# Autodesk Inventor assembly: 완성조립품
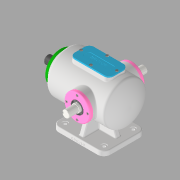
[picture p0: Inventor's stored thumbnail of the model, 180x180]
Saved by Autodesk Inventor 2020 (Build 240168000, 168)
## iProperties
Created: 2021-11
Part Number: 완성조립품
Document SubType Name: Assembly
Designer: Administrator
Author: Administrator
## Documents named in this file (14)
- C:\Users\Administrator\Desktop\71106V1028\완성조립품.iam
- C:\Users\Administrator\Desktop\71106V1028\본체.ipt
- C:\Users\Administrator\Desktop\71106V1028\베어링 6205.ipt
- 베어링 6205.ipt
- C:\Users\Administrator\Desktop\71106V1028\볼트 M4x0.7.ipt
- C:\Users\Administrator\Desktop\71106V1028\부시.ipt
- C:\Users\Administrator\Desktop\71106V1028\상부커버.ipt
- C:\Users\Administrator\Desktop\71106V1028\슬라이드 커버.ipt
- C:\Users\Administrator\Desktop\71106V1028\슬라이드.ipt
- C:\Users\Administrator\Desktop\71106V1028\오일실.ipt
- 오일실.ipt
- C:\Users\Administrator\Desktop\71106V1028\육각머리볼트 M4.ipt
- C:\Users\Administrator\Desktop\71106V1028\축 커버.ipt
- C:\Users\Administrator\Desktop\71106V1028\편심축.ipt
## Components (12 placed, 1 different names)
1. M4x0.7:1 — 각도:1
2. M4x0.7:2
3. M4x0.7:3
4. M4x0.7:4
5. M4x0.7:5 — 각도:2
6. M4x0.7:6
7. M4x0.7:7
8. M4x0.7:8
9. M4x0.7:9 — 각도:3
10. M4x0.7:10
11. M4x0.7:11
12. M4x0.7:12
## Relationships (3: Angle 3)
- 각도:1 [Angle]: M4x0.7:1
- 각도:2 [Angle]: M4x0.7:5
- 각도:3 [Angle]: M4x0.7:9
